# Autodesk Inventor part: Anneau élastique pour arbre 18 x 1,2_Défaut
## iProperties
Shininess: 64.0
Length Units: 11269
Angle Units: 11279
Time Units: 11290
Mass Units: 11283
Length Display Precision: 3
Angle Display Precision: 2
Compacted: True
Part Number: Anneau élastique pour arbre 18 x 1,2_Défaut
Document SubType Name: Modeling
Created: 2006-01
Material: Par défaut
Designer: Fricot
Density: 0.0
Volumn: 0.0
Area: 0.0
PropertySet Name: Model Information
Control State: 0
Master: False
Checked Out: False
Author: Fricot
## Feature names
1. Base1
